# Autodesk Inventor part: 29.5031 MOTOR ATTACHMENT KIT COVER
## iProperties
Created: 2006-12
Part Number: 29.5031 MOTOR ATTACHMENT KIT COVER
Material: Steel
Document SubType Name: Modeling
Designer: Andy Moles
Density: 7.85 g/cm^3
Author: Andy Moles
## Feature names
1. Extrusion1
2. Shell1
3. Fillet1
